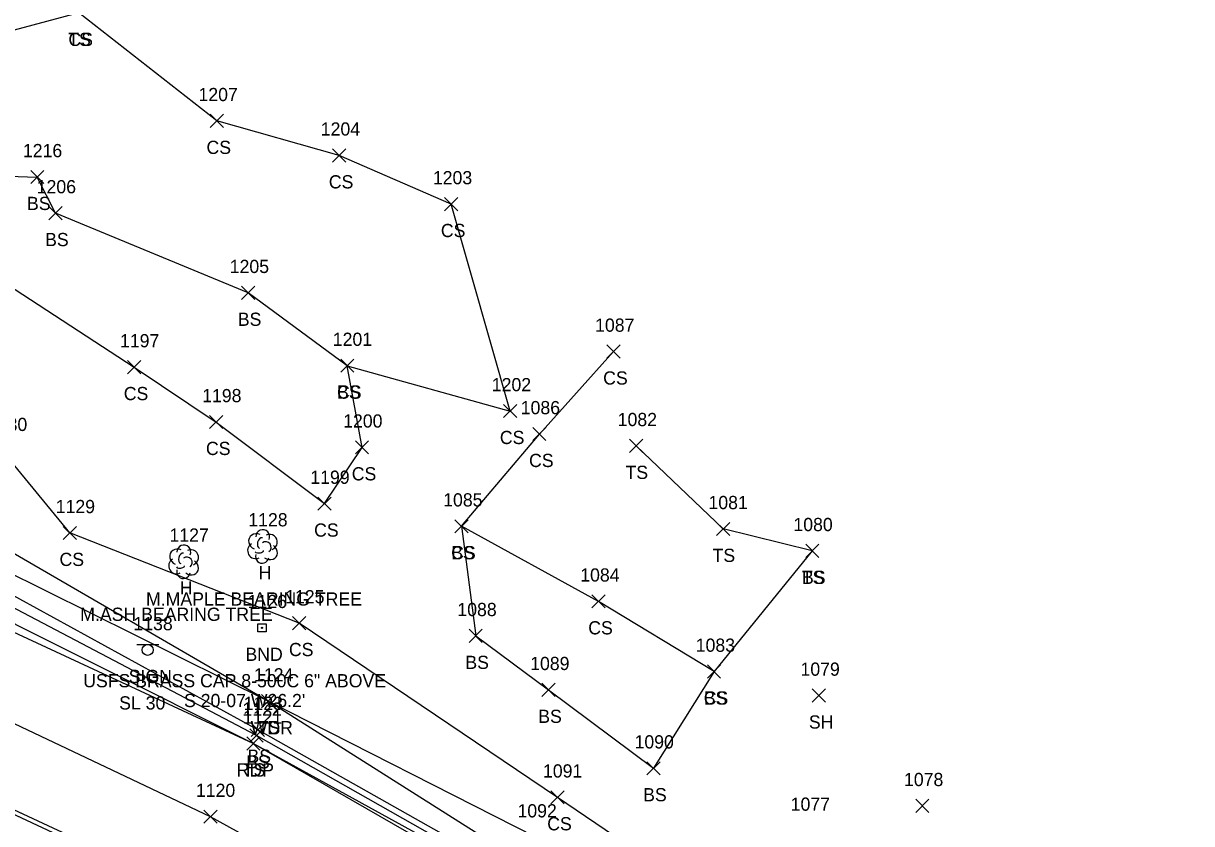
# Model space of a CAD drawing. Extents: x 1499292 to 1501024, y 534584 to 538043.
# Drawn here: x 1500096.6 to 1500273.4, y 537443.3 to 537564.4 of the extents above; entities that cross this region are included whole.
import ezdxf

# ---------------------------------------------------------------- set-up
doc = ezdxf.new("R2010")
doc.units = 0
for name, color, linetype in [('L_A', 7, 'Continuous'), ('L_C', 7, 'Continuous'), ('L_I', 7, 'Continuous'), ('L_TIC', 7, 'Continuous'), ('LAWA', 7, 'Continuous'), ('LELB', 7, 'Continuous'), ('Level 18', 7, 'Continuous'), ('LTD', 7, 'Continuous'), ('M_A', 7, 'Continuous'), ('M_C', 7, 'Continuous'), ('M_I', 7, 'Continuous'), ('P_A', 7, 'Continuous'), ('P_I', 7, 'Continuous'), ('P_TIC', 7, 'Continuous'), ('PET', 7, 'Continuous'), ('PRC', 7, 'Continuous'), ('RGR', 7, 'Continuous'), ('S_A', 7, 'Continuous'), ('S_C', 7, 'Continuous'), ('S_I', 7, 'Continuous'), ('SSGN', 7, 'Continuous')]:
    doc.layers.add(name, color=color, linetype=linetype)

msp = doc.modelspace()

# ---------------------------------------------------------------- linework, layer by layer
at = {"layer": 'L_TIC'}
for points in [[(1500124.84, 537548.67), (1500126.84, 537550.67)], [(1500126.84, 537548.67), (1500124.84, 537550.67)], [(1500143.36, 537543.45), (1500145.36, 537545.45)], [(1500145.36, 537543.45), (1500143.36, 537545.45)], [(1500097.67, 537540.18), (1500099.67, 537542.18)], [(1500099.67, 537540.18), (1500097.67, 537542.18)], [(1500097.67, 537540.18), (1500099.67, 537542.18)], [(1500099.67, 537540.18), (1500097.67, 537542.18)], [(1500160.32, 537536.08), (1500162.32, 537538.08)], [(1500162.32, 537536.08), (1500160.32, 537538.08)], [(1500100.41, 537534.71), (1500102.41, 537536.71)], [(1500102.41, 537534.71), (1500100.41, 537536.71)], [(1500129.58, 537522.64), (1500131.58, 537524.64)], [(1500131.58, 537522.64), (1500129.58, 537524.64)], [(1500184.89, 537513.75), (1500186.89, 537515.75)], [(1500186.89, 537513.75), (1500184.89, 537515.75)], [(1500112.32, 537511.39), (1500114.32, 537513.39)], [(1500114.32, 537511.39), (1500112.32, 537513.39)], [(1500144.6, 537511.61), (1500146.6, 537513.61)], [(1500146.6, 537511.61), (1500144.6, 537513.61)], [(1500144.6, 537511.61), (1500146.6, 537513.61)], [(1500146.6, 537511.61), (1500144.6, 537513.61)], [(1500169.24, 537504.74), (1500171.24, 537506.74)], [(1500171.24, 537504.74), (1500169.24, 537506.74)], [(1500124.76, 537503.08), (1500126.76, 537505.08)], [(1500126.76, 537503.08), (1500124.76, 537505.08)], [(1500173.67, 537501.26), (1500175.67, 537503.26)], [(1500175.67, 537501.26), (1500173.67, 537503.26)], [(1500146.83, 537499.24), (1500148.83, 537501.24)], [(1500148.83, 537499.24), (1500146.83, 537501.24)], [(1500188.31, 537499.46), (1500190.31, 537501.46)], [(1500190.31, 537499.46), (1500188.31, 537501.46)], [(1500141.13, 537490.72), (1500143.13, 537492.72)], [(1500143.13, 537490.72), (1500141.13, 537492.72)], [(1500102.59, 537486.28), (1500104.59, 537488.28)], [(1500104.59, 537486.28), (1500102.59, 537488.28)], [(1500161.88, 537487.29), (1500163.88, 537489.29)], [(1500163.88, 537487.29), (1500161.88, 537489.29)], [(1500161.88, 537487.29), (1500163.88, 537489.29)], [(1500163.88, 537487.29), (1500161.88, 537489.29)], [(1500201.48, 537486.89), (1500203.48, 537488.89)], [(1500203.48, 537486.89), (1500201.48, 537488.89)], [(1500214.99, 537483.56), (1500216.99, 537485.56)], [(1500216.99, 537483.56), (1500214.99, 537485.56)], [(1500214.99, 537483.56), (1500216.99, 537485.56)], [(1500216.99, 537483.56), (1500214.99, 537485.56)], [(1500182.63, 537475.92), (1500184.63, 537477.92)], [(1500184.63, 537475.92), (1500182.63, 537477.92)], [(1500137.31, 537472.63), (1500139.31, 537474.63)], [(1500139.31, 537472.63), (1500137.31, 537474.63)], [(1500164.03, 537470.69), (1500166.03, 537472.69)], [(1500166.03, 537470.69), (1500164.03, 537472.69)], [(1500200.11, 537465.29), (1500202.11, 537467.29)], [(1500202.11, 537465.29), (1500200.11, 537467.29)], [(1500200.11, 537465.29), (1500202.11, 537467.29)], [(1500202.11, 537465.29), (1500200.11, 537467.29)], [(1500175.06, 537462.52), (1500177.06, 537464.52)], [(1500177.06, 537462.52), (1500175.06, 537464.52)], [(1500215.98, 537461.66), (1500217.98, 537463.66)], [(1500217.98, 537461.66), (1500215.98, 537463.66)], [(1500132.61, 537460.8), (1500134.61, 537462.8)], [(1500134.61, 537460.8), (1500132.61, 537462.8)], [(1500132.61, 537460.8), (1500134.61, 537462.8)], [(1500134.61, 537460.8), (1500132.61, 537462.8)], [(1500130.84, 537455.62), (1500132.84, 537457.62)], [(1500132.84, 537455.62), (1500130.84, 537457.62)], [(1500131.04, 537456.48), (1500133.04, 537458.48)], [(1500133.04, 537456.48), (1500131.04, 537458.48)], [(1500130.37, 537454.4), (1500132.37, 537456.4)], [(1500132.37, 537454.4), (1500130.37, 537456.4)], [(1500190.94, 537450.65), (1500192.94, 537452.65)], [(1500192.94, 537450.65), (1500190.94, 537452.65)], [(1500190.94, 537450.65), (1500192.94, 537452.65)], [(1500192.94, 537450.65), (1500190.94, 537452.65)], [(1500176.42, 537446.25), (1500178.42, 537448.25)], [(1500178.42, 537446.25), (1500176.42, 537448.25)], [(1500231.64, 537444.95), (1500233.64, 537446.95)], [(1500233.64, 537444.95), (1500231.64, 537446.95)]]:
    msp.add_lwpolyline(points, dxfattribs=at)
at = {"layer": 'LAWA'}
msp.add_lwpolyline([(1500296.25, 537345.3), (1500256.73, 537378.82), (1500246.41, 537388.79), (1500239.52, 537392.77), (1500228.03, 537398.5), (1500203.66, 537420.68), (1500174.13, 537441.21), (1500133.61, 537461.8), (1500091.85, 537486.02), (1500057.95, 537503.18), (1500037.17, 537516.58), (1500027.18, 537529.7), (1500016.43, 537544.22), (1500024.22, 537554.38), (1500031.9, 537568.77)], dxfattribs=at)
at = {"layer": 'LELB'}
for points in [[(1500290.71, 537339.51), (1500254.04, 537373.68), (1500224.98, 537395.42), (1500200.73, 537412.86), (1500170.41, 537433.92), (1500131.37, 537455.4), (1500083.47, 537479.37), (1500053.62, 537492.68), (1500030.68, 537505.22), (1500012.53, 537513.88), (1499991.95, 537522.3), (1499974.49, 537532.11), (1499955.61, 537546.28), (1499937.72, 537561.94), (1499940.61, 537580.36), (1499943.98, 537590.51), (1499964.26, 537598.71), (1499981.02, 537608.13), (1500000.32, 537612.94)], [(1500292.43, 537341.34), (1500255.06, 537375.07), (1500226.32, 537396.72), (1500201.26, 537414.48), (1500171.22, 537435.38), (1500132.04, 537457.48), (1500085.68, 537482.93), (1500055.74, 537496.91), (1500032.99, 537510.71), (1500014.29, 537519.36), (1499996.72, 537526.9), (1499977.93, 537538.66), (1499965.7, 537556.17), (1499963.9, 537570.61), (1499969.57, 537590.89), (1499978.12, 537601.79)], [(1500291.4, 537340.15), (1500254.56, 537374.3), (1500225.71, 537395.92), (1500201.33, 537413.51), (1500170.9, 537434.45), (1500131.84, 537456.62), (1500084.75, 537481.32), (1500054.37, 537495.03), (1500032.11, 537508.21), (1500014.29, 537516), (1499993.85, 537524.95), (1499976.65, 537535.86), (1499959.1, 537549.21), (1499939.76, 537563.39), (1499940.61, 537580.36)], [(1500071.44, 537533.34), (1500092.78, 537525.77), (1500113.32, 537512.39), (1500125.76, 537504.08), (1500142.13, 537491.72), (1500147.83, 537500.24), (1500145.6, 537512.61), (1500170.24, 537505.74), (1500161.32, 537537.08), (1500144.36, 537544.45), (1500125.84, 537549.67), (1500104.94, 537566.02), (1500074.25, 537557.81), (1500055.63, 537561.64), (1500041.07, 537552.42), (1500031.31, 537541.64)], [(1500045.64, 537522.12), (1500063.4, 537522.25), (1500071.44, 537533.34), (1500085.56, 537541.61), (1500098.67, 537541.18)], [(1500145.6, 537512.61), (1500130.58, 537523.64), (1500101.41, 537535.71), (1500098.67, 537541.18)], [(1500294.64, 537343.13), (1500255.06, 537375.07), (1500255.51, 537377.72), (1500228.03, 537398.5), (1500201.95, 537416.01), (1500172.91, 537436.91), (1500133.61, 537461.8), (1500086.58, 537485.15), (1500056.84, 537500.25), (1500033.98, 537513.25), (1500019.27, 537523.87)], [(1500233.37, 537402.87), (1500206.14, 537427.76), (1500177.42, 537447.25), (1500138.31, 537473.63), (1500103.59, 537487.28), (1500093.41, 537499.72), (1500063.37, 537509.02), (1500045.64, 537522.12)], [(1500201.11, 537466.29), (1500183.63, 537476.92), (1500162.88, 537488.29), (1500174.67, 537502.26), (1500185.89, 537514.75)], [(1500215.99, 537484.56), (1500202.48, 537487.89), (1500189.31, 537500.46)], [(1500162.88, 537488.29), (1500165.03, 537471.69), (1500176.06, 537463.52), (1500191.94, 537451.65)], [(1500215.99, 537484.56), (1500201.11, 537466.29), (1500191.94, 537451.65)]]:
    msp.add_lwpolyline(points, dxfattribs=at)
at = {"layer": 'Level 18'}
msp.add_lwpolyline([(1500132.07, 537473.54), (1500133.32, 537473.54), (1500133.32, 537472.29), (1500132.07, 537472.29)], close=True, dxfattribs=at)
msp.add_circle((1500132.69, 537472.91), 0.0833, dxfattribs=at)
at = {"layer": 'LTD'}
for p, q in [((1500132.74, 537485.28), (1500132.74, 537485.28)), ((1500132.74, 537485.28), (1500132.74, 537485.28)), ((1500120.8, 537482.97), (1500120.8, 537482.97)), ((1500120.8, 537482.97), (1500120.8, 537482.97))]:
    msp.add_line(p, q, dxfattribs=at)
for centre in [(1500132.79, 537486.72), (1500120.85, 537484.41)]:
    msp.add_arc(centre, 1.05, 335.5272, 180.9563, dxfattribs=at)
for centre, major_axis, ratio, start_param, end_param in [((1500131.95, 537485.95), (1.21, -0.51), 0.895232, 1.570796, 4.712389), ((1500132.53, 537485.74), (-0.208, -0.792), 0.645439, 3.141593, 6.283185), ((1500133.24, 537485.12), (-0.5, 0.667), 0.989748, 3.141593, 6.283185), ((1500133.78, 537485.87), (-1.14, -0.48), 0.949671, 1.570796, 4.712389), ((1500120.01, 537483.64), (1.21, -0.51), 0.895232, 1.570796, 4.712389), ((1500120.59, 537483.43), (-0.208, -0.792), 0.645439, 3.141593, 6.283185), ((1500121.84, 537483.56), (-1.14, -0.48), 0.949671, 1.570796, 4.712389), ((1500131.66, 537484.57), (0.58, -1.04), 0.959034, 3.141593, 6.283185), ((1500132.28, 537484.53), (-0.625, -0.083), 0.423636, 0, 3.141593), ((1500133.74, 537484.45), (-1.09, 0.79), 0.841452, 1.570796, 4.712389), ((1500119.72, 537482.26), (0.58, -1.04), 0.959034, 3.141593, 6.283185), ((1500121.3, 537482.81), (-0.5, 0.667), 0.989748, 3.141593, 6.283185), ((1500121.8, 537482.14), (-1.09, 0.79), 0.841452, 1.570796, 4.712389), ((1500132.74, 537483.78), (0.26, 1.06), 0.942809, 1.570796, 4.712389), ((1500120.8, 537481.47), (0.26, 1.06), 0.942809, 1.570796, 4.712389), ((1500120.35, 537482.22), (-0.625, -0.083), 0.423636, 0, 3.141593)]:
    msp.add_ellipse(centre, major_axis=major_axis, ratio=ratio, start_param=start_param, end_param=end_param, dxfattribs=at)
at = {"layer": 'P_TIC'}
for points in [[(1500130.37, 537454.4), (1500132.37, 537456.4)], [(1500132.37, 537454.4), (1500130.37, 537456.4)], [(1500123.89, 537443.32), (1500125.89, 537445.32)], [(1500125.89, 537443.32), (1500123.89, 537445.32)]]:
    msp.add_lwpolyline(points, dxfattribs=at)
at = {"layer": 'PET'}
for points in [[(1500289.78, 537338.29), (1500253.04, 537372.98), (1500224.75, 537395.04), (1500200.64, 537412.65), (1500169.79, 537433.28), (1500131.37, 537455.4), (1500082.94, 537477.86), (1500052.71, 537490.83), (1500028.69, 537501.08), (1500007.59, 537509.93), (1499989.8, 537518.65), (1499972.48, 537528.52), (1499952.08, 537542.88), (1499935.46, 537557.31), (1499909.99, 537586.35), (1499888.96, 537613.55)], [(1500270.13, 537322.4), (1500238.22, 537353.72), (1500209.42, 537377.09), (1500189.13, 537391.85), (1500154.51, 537414.13), (1500120.36, 537433.62), (1500072.03, 537456.11), (1500021.37, 537476.64), (1499998.02, 537486.29), (1499978.14, 537495.01), (1499958.62, 537505.35), (1499935.09, 537521.93), (1499915.79, 537539.45), (1499898.17, 537558.63), (1499884.72, 537577.02)]]:
    msp.add_lwpolyline(points, dxfattribs=at)
at = {"layer": 'PRC'}
msp.add_lwpolyline([(1500278.96, 537330.13), (1500245.16, 537363.32), (1500217.07, 537386.35), (1500194.78, 537402.07), (1500161.59, 537424.07), (1500124.89, 537444.32), (1500077.4, 537466.83), (1500048.03, 537479.39), (1500024.1, 537489.28), (1500002.86, 537498.23), (1499984.27, 537507.12), (1499965.54, 537516.89), (1499943.1, 537532.26), (1499924.7, 537548.4), (1499906.7, 537567.9), (1499892.97, 537586.05), (1499884.57, 537597.67), (1499868.24, 537621.71), (1499849.2, 537650.1), (1499837.66, 537665.34), (1499832.02, 537672.42)], dxfattribs=at)
at = {"layer": 'RGR'}
msp.add_lwpolyline([(1500269.09, 537321.92), (1500237.75, 537353.24), (1500209.1, 537376.73), (1500188.83, 537391.14), (1500154.15, 537413.64), (1500120.04, 537433), (1500071.71, 537455.6), (1500042.55, 537467.65), (1500021.13, 537476.12), (1499999.74, 537485.14), (1499984.16, 537491.49), (1499962.3, 537501.56), (1499943.52, 537510.2), (1499936.88, 537512.97), (1499926.59, 537517.73)], dxfattribs=at)
at = {"layer": 'SSGN'}
for p, q in [((1500113.72, 537470.4), (1500117.06, 537470.4)), ((1500115.37, 537469.57), (1500115.37, 537469.57))]:
    msp.add_line(p, q, dxfattribs=at)
msp.add_circle((1500115.37, 537469.57), 0.833, dxfattribs=at)

# ---------------------------------------------------------------- texts
at = {"layer": 'L_A'}
for s, p in [('TS', (1500103.35, 537561.02)), ('CS', (1500103.38, 537561.02)), ('CS', (1500124.28, 537544.67)), ('CS', (1500142.8, 537539.45)), ('BS', (1500097.11, 537536.18)), ('BS', (1500097.11, 537536.18)), ('CS', (1500159.76, 537532.08)), ('BS', (1500099.85, 537530.71)), ('BS', (1500129.02, 537518.64)), ('CS', (1500184.33, 537509.75)), ('CS', (1500111.76, 537507.39)), ('CS', (1500144.04, 537507.61)), ('BS', (1500144.04, 537507.61)), ('CS', (1500168.69, 537500.74)), ('CS', (1500124.2, 537499.08)), ('CS', (1500173.11, 537497.26)), ('CS', (1500146.27, 537495.24)), ('TS', (1500187.71, 537495.46)), ('CS', (1500140.57, 537486.72)), ('CS', (1500102.03, 537482.28)), ('CS', (1500161.32, 537483.29)), ('BS', (1500161.32, 537483.29)), ('TS', (1500200.89, 537482.89)), ('H', (1500132.17, 537480.28)), ('TS', (1500214.4, 537479.56)), ('BS', (1500214.43, 537479.56)), ('H', (1500120.24, 537477.97)), ('CS', (1500182.07, 537471.92)), ('CS', (1500136.76, 537468.63)), ('BS', (1500163.47, 537466.69)), ('CS', (1500199.55, 537461.29)), ('BS', (1500199.55, 537461.29)), ('BS', (1500174.5, 537458.52)), ('SH', (1500215.47, 537457.66)), ('WDR', (1500130.97, 537456.8)), ('TS', (1500132.02, 537456.8)), ('BS', (1500130.48, 537452.48)), ('TS', (1500129.78, 537450.4)), ('BS', (1500130.28, 537451.62)), ('BS', (1500190.38, 537446.65)), ('BS', (1500190.38, 537446.65)), ('CS', (1500175.86, 537442.25))]:
    msp.add_text(s, height=2, dxfattribs=at).set_placement(p)
at = {"layer": 'L_C'}
for s, p in [('M.MAPLE BEARING TREE', (1500115.13, 537476.28)), ('M.ASH BEARING TREE', (1500105.17, 537473.97))]:
    msp.add_text(s, height=2, dxfattribs=at).set_placement(p)
at = {"layer": 'L_I'}
for s, p in [('1207', (1500123.07, 537552.67)), ('1204', (1500141.58, 537547.45)), ('1216', (1500096.49, 537544.18)), ('1216', (1500096.49, 537544.18)), ('1206', (1500098.58, 537538.71)), ('1203', (1500158.55, 537540.08)), ('1205', (1500127.8, 537526.64)), ('1087', (1500183.11, 537517.75)), ('1197', (1500111.19, 537515.39)), ('1201', (1500143.4, 537515.61)), ('1201', (1500143.4, 537515.61)), ('1202', (1500167.47, 537508.74)), ('1198', (1500123.63, 537507.08)), ('1086', (1500171.85, 537505.26)), ('1082', (1500186.53, 537503.46)), ('1130', (1500091.2, 537502.72)), ('1200', (1500144.97, 537503.24)), ('1199', (1500140, 537494.72)), ('1085', (1500160.11, 537491.29)), ('1085', (1500160.11, 537491.29)), ('1129', (1500101.46, 537490.28)), ('1081', (1500200.27, 537490.89)), ('1128', (1500130.61, 537488.28)), ('1080', (1500213.13, 537487.56)), ('1080', (1500213.13, 537487.56)), ('1127', (1500118.68, 537485.97)), ('1084', (1500180.86, 537479.92)), ('1125', (1500136.19, 537476.63)), ('1088', (1500162.26, 537474.69)), ('1083', (1500198.34, 537469.29)), ('1083', (1500198.34, 537469.29)), ('1089', (1500173.28, 537466.52)), ('1124', (1500131.48, 537464.8)), ('1124', (1500131.48, 537464.8)), ('1079', (1500214.2, 537465.66)), ('1122', (1500129.72, 537459.62)), ('1123', (1500129.91, 537460.48)), ('1121', (1500129.81, 537458.4)), ('1090', (1500189.08, 537454.65)), ('1090', (1500189.08, 537454.65)), ('1091', (1500175.22, 537450.25)), ('1078', (1500229.87, 537448.95)), ('1077', (1500212.72, 537445.22)), ('1092', (1500171.36, 537444.21))]:
    msp.add_text(s, height=2, dxfattribs=at).set_placement(p)
at = {"layer": 'M_A'}
msp.add_text('BND', height=2, dxfattribs=at).set_placement((1500130.18, 537467.91))
at = {"layer": 'M_C'}
for s, p in [('USFS BRASS CAP 8-500C 6" ABOVE', (1500105.62, 537463.91)), ("S 20-07 W26.2'", (1500120.88, 537460.91))]:
    msp.add_text(s, height=2, dxfattribs=at).set_placement(p)
at = {"layer": 'M_I'}
msp.add_text('1126', height=2, dxfattribs=at).set_placement((1500130.51, 537475.91))
at = {"layer": 'P_A'}
msp.add_text('RDP', height=2, dxfattribs=at).set_placement((1500128.85, 537450.4))
at = {"layer": 'P_I'}
for s, p in [('1121', (1500129.81, 537458.4)), ('1120', (1500122.68, 537447.32))]:
    msp.add_text(s, height=2, dxfattribs=at).set_placement(p)
at = {"layer": 'S_A'}
msp.add_text('SIGN', height=2, dxfattribs=at).set_placement((1500112.51, 537464.55))
at = {"layer": 'S_C'}
msp.add_text('SL 30', height=2, dxfattribs=at).set_placement((1500111.06, 537460.55))
at = {"layer": 'S_I'}
msp.add_text('1138', height=2, dxfattribs=at).set_placement((1500113.22, 537472.55))

doc.saveas('drawing.dxf')
